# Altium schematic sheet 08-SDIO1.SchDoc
size A4; SheetNumber: 0; SheetTotal: 0
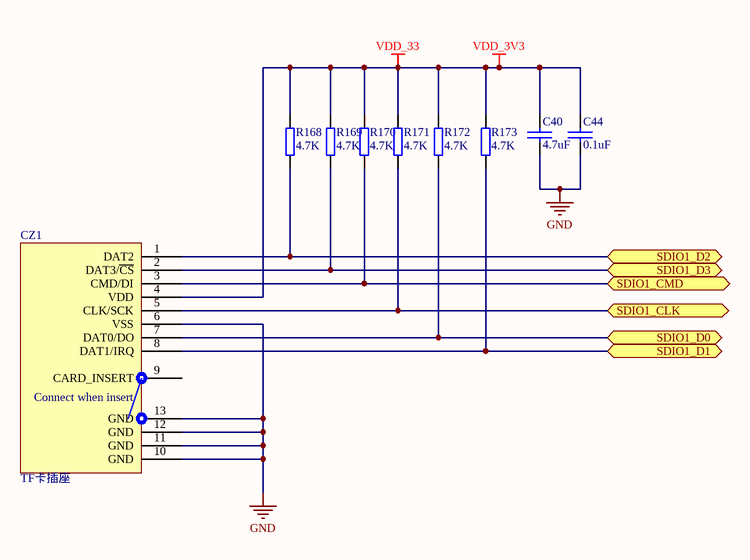
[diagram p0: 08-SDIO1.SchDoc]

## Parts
C40  4.7uF  [C0402]
C44  0.1uF  [C0402]
CZ1  TF卡插座  [SDIO卡座(8P)]
R168  4.7K  [R0402]
R169  4.7K  [R0402]
R170  4.7K  [R0402]
R171  4.7K  [R0402]
R172  4.7K  [R0402]
R173  4.7K  [R0402]

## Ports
SDIO1_CLK (bidir), SDIO1_CMD (bidir), SDIO1_D0 (bidir), SDIO1_D1 (bidir), SDIO1_D2 (bidir), SDIO1_D3 (bidir)

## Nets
GND: C40.2 C44.2 CZ1.6(VSS) CZ1.10(GND) CZ1.11(GND) CZ1.12(GND) CZ1.13(GND)
VDD_33: C40.1 C44.1 CZ1.4(VDD) R168.1 R169.1 R170.1 R171.1 R172.1 R173.1  [also labelled VDD_3V3]
SDIO1_CLK: CZ1.5(CLK/SCK) R171.2 ; port SDIO1_CLK
SDIO1_CMD: CZ1.3(CMD/DI) R170.2 ; port SDIO1_CMD
SDIO1_D0: CZ1.7(DAT0/DO) R172.2 ; port SDIO1_D0
SDIO1_D1: CZ1.8(DAT1/IRQ) R173.2 ; port SDIO1_D1
SDIO1_D2: CZ1.1(DAT2) R168.2 ; port SDIO1_D2
SDIO1_D3: CZ1.2(DAT3/~{CS}) R169.2 ; port SDIO1_D3

Not connected (* = marked no-connect by the designer): CZ1 9(CARD_INSERT)

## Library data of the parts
C40 C44 = 电容: Capacitor
CZ1 = SD_CARD-Push: 自弹式TF卡卡座
R168-R173 = 电阻Ω: Resistor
